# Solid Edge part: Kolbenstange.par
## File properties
Username: ahadarics
Dokumentum tartalom típus: 0
Author: ahadarics
Last saved by: ahadarics
Revision: 92
Sűrűség: 0,000 kg/m^3
Pontosság: 0,990
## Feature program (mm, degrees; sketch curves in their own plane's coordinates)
base feature "unnamed BaseFeature 1"
thread "unnamed Thread 1"
sketch for "Kihúzás_1" plane through (59.75, 0, 0) normal (1, 0, 0) x-axis (0, -1, 0)
  circle centre (0, 0) radius 10
extrude "Kihúzás_1" add finite 32 along -normal
chamfer "Letörés_1" setback 0.4
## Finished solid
Body 1: solid body, 13 faces, 23 edges, 12 vertices.
  Faces by surface: plane 9, cylinder 3, cone 1
  Edges by curve: line 12, circle 11
Bounding box of the edges (mm): 1093.500 x 20.000 x 20.000, from (-1033.75, -10, -10) to (59.75, 10, 10).
Cylindrical faces by radius (mm): R4 x2, R10 x1
Conical faces (half-angle, radius in mm at the cone's reference point): 45 deg R3.6 x1
Planar faces by outward normal: +x 3, +z 1, -x 4, -z 1
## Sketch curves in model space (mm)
circle centre (59.75, 0, 0) radius 10
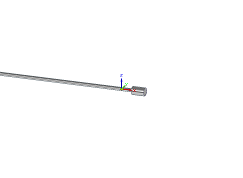
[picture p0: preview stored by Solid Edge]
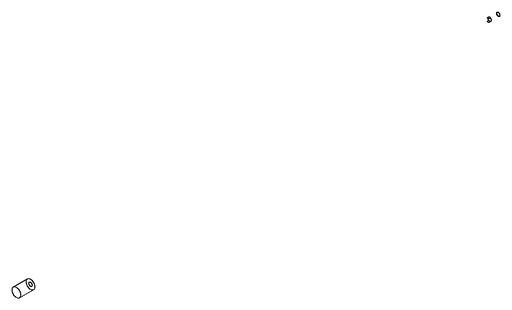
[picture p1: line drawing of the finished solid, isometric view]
